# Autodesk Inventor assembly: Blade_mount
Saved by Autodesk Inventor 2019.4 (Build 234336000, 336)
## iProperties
Created: 2020-04
Part Number: Blade_mount
Document SubType Name: Assembly
Designer: Administrator
Title: Blade_mount v18
Author: Administrator
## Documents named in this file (10)
- c:\worker\convert-fusion-r03\tmp\job-1\48\output\files\ccae6ef3-9f0e-42ff-b199-3a2c6474057a\Blade_mount v18_1.iam
- c:\worker\convert-fusion-r03\tmp\job-1\48\output\files\ccae6ef3-9f0e-42ff-b199-3a2c6474057a\Component1.ipt
- c:\worker\convert-fusion-r03\tmp\job-1\48\output\files\ccae6ef3-9f0e-42ff-b199-3a2c6474057a\Component2.ipt
- c:\worker\convert-fusion-r03\tmp\job-1\48\output\files\ccae6ef3-9f0e-42ff-b199-3a2c6474057a\Component3.ipt
- c:\worker\convert-fusion-r03\tmp\job-1\48\output\files\ccae6ef3-9f0e-42ff-b199-3a2c6474057a\Component4.ipt
- c:\worker\convert-fusion-r03\tmp\job-1\48\output\files\ccae6ef3-9f0e-42ff-b199-3a2c6474057a\Component5.ipt
- c:\worker\convert-fusion-r03\tmp\job-1\48\output\files\ccae6ef3-9f0e-42ff-b199-3a2c6474057a\Component6.ipt
- c:\worker\convert-fusion-r03\tmp\job-1\48\output\files\ccae6ef3-9f0e-42ff-b199-3a2c6474057a\Component7.ipt
- c:\worker\convert-fusion-r03\tmp\job-1\48\output\files\ccae6ef3-9f0e-42ff-b199-3a2c6474057a\Component8.ipt
- c:\worker\convert-fusion-r03\tmp\job-1\48\output\files\ccae6ef3-9f0e-42ff-b199-3a2c6474057a\Component9.ipt
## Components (9 placed, 9 different names)
1. Component1:1
2. Component2:1
3. Component3:1
4. Component4:1
5. Component5:1
6. Component6:1
7. Component7:1
8. Component8:1
9. Component9:1
